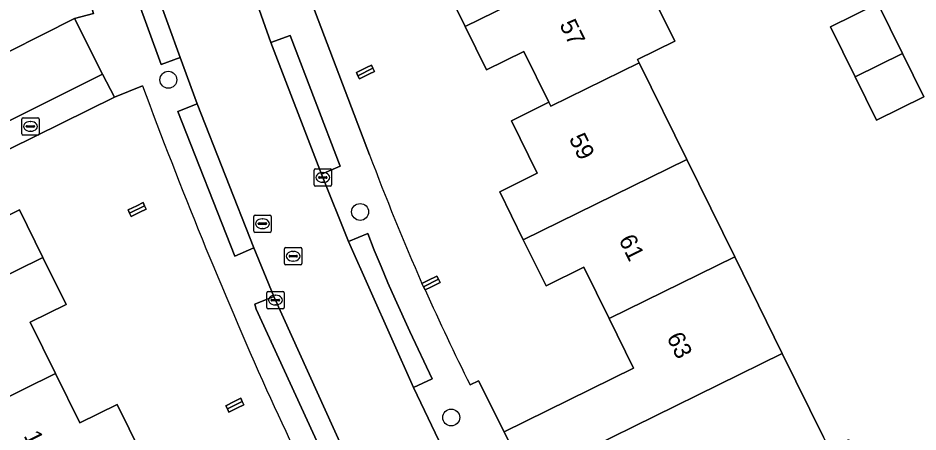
# Model space of a CAD drawing. Extents: x 157793 to 159380, y 380877 to 382313.
# Drawn here: x 158362 to 158414.2, y 381566.4 to 381590.4 of the extents above; entities that cross this region are included whole.
import ezdxf

# ---------------------------------------------------------------- set-up
doc = ezdxf.new("R2010")
doc.units = 0
for name, color, linetype in [('IMGEO_Boom', 7, 'Continuous'), ('IMGEO_Erf', 7, 'Continuous'), ('IMGEO_Kolk', 7, 'Continuous'), ('IMGEO_Pand', 7, 'Continuous'), ('IMGEO_Pand_nummerreeks', 7, 'Continuous'), ('IMGEO_Rijbaan_lokaal_open', 7, 'Continuous'), ('IMGEO_Rioolput', 7, 'Continuous'), ('IMGEO_Voetpad_open', 7, 'Continuous')]:
    doc.layers.add(name, color=color, linetype=linetype)

msp = doc.modelspace()

# ---------------------------------------------------------------- linework, layer by layer
at = {"layer": 'IMGEO_Boom'}
for centre in [(158370.732, 381586.792), (158381.84, 381579.129), (158387.121, 381567.211)]:
    msp.add_circle(centre, 0.489, dxfattribs=at)
at = {"layer": 'IMGEO_Erf'}
for points in [[(158356.876, 381585.543), (158358.253, 381582.801), (158361.236, 381584.267), (158359.62, 381587.484), (158365.3, 381590.338), (158366.389, 381590.642), (158363.671, 381599.661), (158359.523, 381613.428)], [(158388.212, 381569.097), (158388.702, 381569.336), (158390.187, 381566.383), (158397.688, 381570.074), (158396.271, 381572.954), (158394.809, 381575.924), (158392.612, 381574.843), (158391.296, 381577.517), (158389.927, 381580.297), (158392.107, 381581.37), (158390.606, 381584.418), (158392.777, 381585.486), (158391.328, 381588.431), (158389.17, 381587.369), (158387.933, 381589.882), (158386.449, 381592.897), (158388.607, 381593.959), (158387.233, 381596.753), (158380.16, 381593.447), (158378.526, 381592.633), (158382.383, 381582.444)], [(158397.374, 381594.525), (158400.079, 381589.03), (158397.912, 381587.964), (158398.004, 381587.778), (158400.762, 381582.173), (158403.54, 381576.529), (158406.301, 381570.918), (158408.691, 381566.062), (158408.949, 381565.538), (158409.028, 381565.378), (158410.156, 381565.932), (158413.001, 381560.152), (158415.756, 381561.507)], [(158414.496, 381585.807), (158411.752, 381584.456), (158410.515, 381586.97), (158409.093, 381589.86), (158411.837, 381591.211)], [(158369.236, 381586.441), (158367.61, 381585.777), (158358.447, 381581.259)], [(158359.962, 381578.192), (158362.103, 381579.249), (158363.465, 381576.49), (158364.809, 381573.766), (158362.727, 381572.738), (158364.193, 381569.769), (158365.607, 381566.904), (158367.759, 381567.966), (158369.156, 381565.135)], [(158385.424, 381574.982), (158385.755, 381575.145), (158386.292, 381575.41), (158386.381, 381575.228), (158386.475, 381575.038), (158385.938, 381574.773), (158385.607, 381574.61)]]:
    msp.add_lwpolyline(points, dxfattribs=at)
for points in [[(158382.387, 381587.133), (158381.808, 381586.847), (158381.718, 381587.029), (158381.625, 381587.219), (158382.204, 381587.505), (158382.493, 381587.647), (158382.581, 381587.467), (158382.676, 381587.275)], [(158368.396, 381579.242), (158368.897, 381579.489), (158369.264, 381579.67), (158369.355, 381579.485), (158369.447, 381579.298), (158369.081, 381579.117), (158368.579, 381578.87), (158368.489, 381579.053)], [(158374.24, 381567.523), (158374.149, 381567.708), (158374.057, 381567.895), (158374.546, 381568.136), (158374.925, 381568.323), (158375.017, 381568.135), (158375.108, 381567.951), (158374.729, 381567.764)]]:
    msp.add_lwpolyline(points, close=True, dxfattribs=at)
for centre, radius, start, end in [((158646.568, 381689.148), 295.739, 200.32153, 204.01013), ((158536.316, 381640.826), 164.633, 200.77015, 203.57474), ((158534.872, 381641.769), 163.678, 204.22437, 206.35893), ((158919.563, 381819.876), 598.364, 204.808304, 206.427269)]:
    msp.add_arc(centre, radius, start, end, dxfattribs=at)
at = {"layer": 'IMGEO_Kolk'}
for p, q in [((158362.242, 381583.661), (158362.242, 381584.513)), ((158362.317, 381584.587), (158363.169, 381584.587)), ((158363.243, 381584.513), (158363.243, 381583.661)), ((158362.501, 381584.081), (158362.501, 381584.093)), ((158362.939, 381584.044), (158362.541, 381584.044)), ((158362.544, 381584.13), (158362.942, 381584.13)), ((158362.73, 381584.367), (158362.755, 381584.367)), ((158362.985, 381584.093), (158362.985, 381584.081)), ((158363.169, 381583.587), (158362.317, 381583.587)), ((158362.753, 381583.807), (158362.728, 381583.807)), ((158379.18, 381580.701), (158379.18, 381581.553)), ((158379.255, 381581.627), (158380.107, 381581.627)), ((158379.668, 381581.407), (158379.693, 381581.407)), ((158380.181, 381581.553), (158380.181, 381580.701)), ((158379.439, 381581.121), (158379.439, 381581.133)), ((158379.877, 381581.084), (158379.479, 381581.084)), ((158379.482, 381581.17), (158379.88, 381581.17)), ((158379.691, 381580.847), (158379.666, 381580.847)), ((158379.923, 381581.133), (158379.923, 381581.121)), ((158380.107, 381580.627), (158379.255, 381580.627)), ((158376.509, 381574.518), (158377.361, 381574.518)), ((158376.434, 381573.592), (158376.434, 381574.444)), ((158376.693, 381574.012), (158376.693, 381574.024)), ((158376.736, 381574.061), (158377.134, 381574.061)), ((158376.922, 381574.298), (158376.947, 381574.298)), ((158377.177, 381574.024), (158377.177, 381574.012)), ((158377.435, 381574.444), (158377.435, 381573.592)), ((158377.361, 381573.518), (158376.509, 381573.518)), ((158377.131, 381573.975), (158376.733, 381573.975)), ((158376.945, 381573.738), (158376.92, 381573.738))]:
    msp.add_line(p, q, dxfattribs=at)
for points in [[(158362.242, 381583.661), (158362.242, 381584.513)], [(158362.317, 381584.587), (158363.169, 381584.587)], [(158363.243, 381584.513), (158363.243, 381583.661)], [(158363.169, 381583.587), (158362.317, 381583.587)], [(158379.18, 381580.701), (158379.18, 381581.553)], [(158379.255, 381581.627), (158380.107, 381581.627)], [(158380.181, 381581.553), (158380.181, 381580.701)], [(158380.107, 381580.627), (158379.255, 381580.627)], [(158376.509, 381574.518), (158377.361, 381574.518)], [(158376.434, 381573.592), (158376.434, 381574.444)], [(158377.435, 381574.444), (158377.435, 381573.592)], [(158377.361, 381573.518), (158376.509, 381573.518)]]:
    msp.add_lwpolyline(points, dxfattribs=at)
for centre, radius, start, end in [((158362.319, 381584.511), 0.0765, 91.552, 178.448), ((158362.319, 381584.511), 0.0765, 91.552, 178.448), ((158363.167, 381584.511), 0.0765, 1.552, 88.448), ((158363.167, 381584.511), 0.0765, 1.552, 88.448), ((158362.541, 381584.09), 0.0403, 85.8775, 175.7526), ((158362.538, 381584.08), 0.0366, 178.938, 274.7102), ((158362.942, 381584.087), 0.043, 264.8664, 352.4533), ((158362.946, 381584.092), 0.0386, 1.7309, 96.639), ((158362.319, 381583.663), 0.0765, 181.552, 268.448), ((158362.319, 381583.663), 0.0765, 181.552, 268.448), ((158363.167, 381583.663), 0.0765, 271.552, 358.448), ((158363.167, 381583.663), 0.0765, 271.552, 358.448), ((158379.257, 381581.551), 0.0765, 91.552, 178.448), ((158379.257, 381581.551), 0.0765, 91.552, 178.448), ((158380.105, 381581.551), 0.0765, 1.552, 88.448), ((158380.105, 381581.551), 0.0765, 1.552, 88.448), ((158379.479, 381581.13), 0.0403, 85.8775, 175.7526), ((158379.476, 381581.12), 0.0366, 178.938, 274.7102), ((158379.88, 381581.127), 0.043, 264.8664, 352.4533), ((158379.884, 381581.132), 0.0386, 1.7309, 96.639), ((158379.257, 381580.703), 0.0765, 181.552, 268.448), ((158379.257, 381580.703), 0.0765, 181.552, 268.448), ((158380.105, 381580.703), 0.0765, 271.552, 358.448), ((158380.105, 381580.703), 0.0765, 271.552, 358.448), ((158376.511, 381574.442), 0.0765, 91.552, 178.448), ((158376.511, 381574.442), 0.0765, 91.552, 178.448), ((158377.359, 381574.442), 0.0765, 1.552, 88.448), ((158377.359, 381574.442), 0.0765, 1.552, 88.448), ((158376.733, 381574.021), 0.0403, 85.8775, 175.7526), ((158376.73, 381574.011), 0.0366, 178.938, 274.7102), ((158377.134, 381574.018), 0.043, 264.8664, 352.4533), ((158377.138, 381574.023), 0.0386, 1.7309, 96.639), ((158376.511, 381573.594), 0.0765, 181.552, 268.448), ((158376.511, 381573.594), 0.0765, 181.552, 268.448), ((158377.359, 381573.594), 0.0765, 271.552, 358.448), ((158377.359, 381573.594), 0.0765, 271.552, 358.448)]:
    msp.add_arc(centre, radius, start, end, dxfattribs=at)
for centre, major_axis, ratio, start_param, end_param in [((158362.729, 381584.087), (-0.387, 0.002), 0.722429, 4.712389, 7.853982), ((158362.754, 381584.087), (-0.39, 0.002), 0.717154, 1.570796, 4.712389), ((158379.667, 381581.127), (-0.387, 0.002), 0.722429, 4.712389, 7.853982), ((158379.692, 381581.127), (-0.39, 0.002), 0.717154, 1.570796, 4.712389), ((158376.921, 381574.018), (-0.387, 0.002), 0.722429, 4.712389, 7.853982), ((158376.946, 381574.018), (-0.39, 0.002), 0.717154, 1.570796, 4.712389)]:
    msp.add_ellipse(centre, major_axis=major_axis, ratio=ratio, start_param=start_param, end_param=end_param, dxfattribs=at)
at = {"layer": 'IMGEO_Pand'}
for points in [[(158387.933, 381589.882), (158397.374, 381594.525), (158396.722, 381595.85), (158394.514, 381600.336), (158387.233, 381596.753), (158388.607, 381593.959), (158386.449, 381592.897)], [(158387.933, 381589.882), (158389.17, 381587.369), (158391.328, 381588.431), (158392.777, 381585.486), (158392.885, 381585.266), (158398.004, 381587.778), (158397.912, 381587.964), (158400.079, 381589.03), (158397.374, 381594.525)], [(158410.515, 381586.97), (158413.259, 381588.32), (158411.837, 381591.211), (158409.093, 381589.86)], [(158366.916, 381587.12), (158365.3, 381590.338), (158359.62, 381587.484), (158361.236, 381584.267)], [(158410.515, 381586.97), (158411.752, 381584.456), (158414.496, 381585.807), (158413.259, 381588.32)], [(158381.718, 381587.029), (158382.581, 381587.467), (158382.493, 381587.647), (158382.204, 381587.505), (158381.625, 381587.219)], [(158400.762, 381582.173), (158398.004, 381587.778), (158392.885, 381585.266), (158392.777, 381585.486), (158390.606, 381584.418), (158392.107, 381581.37), (158389.927, 381580.297), (158391.296, 381577.517)], [(158382.581, 381587.467), (158381.718, 381587.029), (158381.808, 381586.847), (158382.387, 381587.133), (158382.676, 381587.275)], [(158400.762, 381582.173), (158391.296, 381577.517), (158392.612, 381574.843), (158394.809, 381575.924), (158396.271, 381572.954), (158403.54, 381576.529)], [(158354.103, 381571.867), (158363.465, 381576.49), (158362.103, 381579.249), (158359.962, 381578.192), (158358.447, 381581.259), (158351.226, 381577.694)], [(158368.489, 381579.053), (158369.355, 381579.485), (158369.264, 381579.67), (158368.897, 381579.489), (158368.396, 381579.242)], [(158369.355, 381579.485), (158368.489, 381579.053), (158368.579, 381578.87), (158369.081, 381579.117), (158369.447, 381579.298)], [(158356.912, 381566.175), (158364.193, 381569.769), (158362.727, 381572.738), (158364.809, 381573.766), (158363.465, 381576.49), (158354.103, 381571.867)], [(158391.533, 381563.648), (158406.301, 381570.918), (158403.54, 381576.529), (158396.271, 381572.954), (158397.688, 381570.074), (158390.187, 381566.383)], [(158385.517, 381574.792), (158386.381, 381575.228), (158386.292, 381575.41), (158385.755, 381575.145), (158385.424, 381574.982)], [(158386.381, 381575.228), (158385.517, 381574.792), (158385.607, 381574.61), (158385.938, 381574.773), (158386.475, 381575.038)], [(158409.028, 381565.378), (158408.949, 381565.538), (158408.691, 381566.062), (158406.301, 381570.918), (158391.533, 381563.648), (158392.879, 381560.912), (158400.34, 381564.584), (158401.927, 381561.36), (158403.032, 381561.904), (158402.93, 381562.112), (158409.036, 381565.124), (158408.935, 381565.332)], [(158364.193, 381569.769), (158356.912, 381566.175), (158354.295, 381564.883), (158355.562, 381562.319), (158358.171, 381563.626), (158359.724, 381560.479), (158369.156, 381565.135), (158367.759, 381567.966), (158365.607, 381566.904)], [(158375.017, 381568.135), (158374.925, 381568.323), (158374.546, 381568.136), (158374.057, 381567.895), (158374.149, 381567.708)], [(158375.017, 381568.135), (158374.149, 381567.708), (158374.24, 381567.523), (158374.729, 381567.764), (158375.108, 381567.951)]]:
    msp.add_lwpolyline(points, close=True, dxfattribs=at)
at = {"layer": 'IMGEO_Rijbaan_lokaal_open'}
msp.add_lwpolyline([(158386.819, 381564.982), (158384.933, 381568.948), (158381.167, 381577.418), (158379.602, 381581.325), (158376.667, 381588.951), (158374.56, 381594.93), (158371.964, 381603.521), (158369.282, 381612.393), (158368.776, 381614.35), (158363.671, 381612.88), (158364.288, 381610.829), (158368.864, 381595.592), (158369.995, 381592.049), (158371.408, 381588.08), (158372.398, 381585.387), (158375.686, 381577.039), (158376.843, 381574.222), (158380.835, 381565.391), (158382.561, 381561.814), (158386.047, 381554.706), (158388.014, 381550.791), (158391.624, 381543.519), (158392.052, 381542.802), (158392.965, 381540.911)], dxfattribs=at)
at = {"layer": 'IMGEO_Rioolput'}
for p, q in [((158375.681, 381578.02), (158375.681, 381578.872)), ((158375.756, 381578.946), (158376.608, 381578.946)), ((158376.169, 381578.726), (158376.194, 381578.726)), ((158376.682, 381578.872), (158376.682, 381578.02)), ((158375.94, 381578.44), (158375.94, 381578.452)), ((158376.378, 381578.403), (158375.98, 381578.403)), ((158375.983, 381578.489), (158376.381, 381578.489)), ((158376.192, 381578.166), (158376.167, 381578.166)), ((158376.424, 381578.452), (158376.424, 381578.44)), ((158376.608, 381577.946), (158375.756, 381577.946)), ((158377.464, 381576.136), (158377.464, 381576.988)), ((158377.539, 381577.062), (158378.391, 381577.062)), ((158377.766, 381576.605), (158378.164, 381576.605)), ((158377.952, 381576.842), (158377.977, 381576.842)), ((158378.465, 381576.988), (158378.465, 381576.136)), ((158377.723, 381576.556), (158377.723, 381576.568)), ((158378.161, 381576.519), (158377.763, 381576.519)), ((158377.975, 381576.282), (158377.95, 381576.282)), ((158378.207, 381576.568), (158378.207, 381576.556)), ((158378.391, 381576.062), (158377.539, 381576.062))]:
    msp.add_line(p, q, dxfattribs=at)
for points in [[(158375.681, 381578.02), (158375.681, 381578.872)], [(158375.756, 381578.946), (158376.608, 381578.946)], [(158376.682, 381578.872), (158376.682, 381578.02)], [(158376.608, 381577.946), (158375.756, 381577.946)], [(158377.464, 381576.136), (158377.464, 381576.988)], [(158377.539, 381577.062), (158378.391, 381577.062)], [(158378.465, 381576.988), (158378.465, 381576.136)], [(158378.391, 381576.062), (158377.539, 381576.062)]]:
    msp.add_lwpolyline(points, dxfattribs=at)
for centre, radius, start, end in [((158375.758, 381578.87), 0.0765, 91.552, 178.448), ((158375.758, 381578.87), 0.0765, 91.552, 178.448), ((158376.606, 381578.87), 0.0765, 1.552, 88.448), ((158376.606, 381578.87), 0.0765, 1.552, 88.448), ((158375.98, 381578.449), 0.0403, 85.8775, 175.7526), ((158375.977, 381578.439), 0.0366, 178.938, 274.7102), ((158376.381, 381578.446), 0.043, 264.8664, 352.4533), ((158376.385, 381578.451), 0.0386, 1.7309, 96.639), ((158375.758, 381578.022), 0.0765, 181.552, 268.448), ((158375.758, 381578.022), 0.0765, 181.552, 268.448), ((158376.606, 381578.022), 0.0765, 271.552, 358.448), ((158376.606, 381578.022), 0.0765, 271.552, 358.448), ((158377.541, 381576.986), 0.0765, 91.552, 178.448), ((158377.541, 381576.986), 0.0765, 91.552, 178.448), ((158377.763, 381576.565), 0.0403, 85.8775, 175.7526), ((158378.168, 381576.567), 0.0386, 1.7309, 96.639), ((158378.389, 381576.986), 0.0765, 1.552, 88.448), ((158378.389, 381576.986), 0.0765, 1.552, 88.448), ((158377.541, 381576.138), 0.0765, 181.552, 268.448), ((158377.541, 381576.138), 0.0765, 181.552, 268.448), ((158377.76, 381576.555), 0.0366, 178.938, 274.7102), ((158378.164, 381576.562), 0.043, 264.8664, 352.4533), ((158378.389, 381576.138), 0.0765, 271.552, 358.448), ((158378.389, 381576.138), 0.0765, 271.552, 358.448)]:
    msp.add_arc(centre, radius, start, end, dxfattribs=at)
for centre, major_axis, ratio, start_param, end_param in [((158376.168, 381578.446), (-0.387, 0.002), 0.722429, 4.712389, 7.853982), ((158376.193, 381578.446), (-0.39, 0.002), 0.717154, 1.570796, 4.712389), ((158377.951, 381576.562), (-0.387, 0.002), 0.722429, 4.712389, 7.853982), ((158377.976, 381576.562), (-0.39, 0.002), 0.717154, 1.570796, 4.712389)]:
    msp.add_ellipse(centre, major_axis=major_axis, ratio=ratio, start_param=start_param, end_param=end_param, dxfattribs=at)
at = {"layer": 'IMGEO_Voetpad_open'}
for points in [[(158359.523, 381613.428), (158363.671, 381599.661), (158366.389, 381590.642), (158365.3, 381590.338), (158366.916, 381587.12), (158367.61, 381585.777), (158369.236, 381586.441)], [(158374.56, 381594.93), (158376.667, 381588.951), (158377.786, 381589.363), (158380.682, 381581.779), (158379.602, 381581.325), (158381.167, 381577.418), (158382.279, 381577.87), (158382.66, 381576.914), (158383.053, 381575.963), (158383.455, 381575.016), (158383.868, 381574.073), (158384.725, 381572.202), (158386.008, 381569.445), (158384.933, 381568.948), (158386.819, 381564.982), (158387.899, 381565.529), (158391.435, 381558.264), (158390.388, 381557.763), (158392.105, 381554.248), (158393.177, 381554.8), (158396.917, 381547.243), (158395.863, 381546.7), (158397.356, 381543.737), (158402.431, 381546.2)], [(158382.383, 381582.444), (158378.526, 381592.633), (158380.16, 381593.447), (158379.644, 381594.891)], [(158392.965, 381540.911), (158392.052, 381542.802), (158391.624, 381543.519), (158390.547, 381543.006), (158386.953, 381550.259), (158388.014, 381550.791), (158386.047, 381554.706), (158384.979, 381554.194), (158381.459, 381561.337), (158382.561, 381561.814), (158380.835, 381565.391), (158379.757, 381564.906), (158375.828, 381573.501), (158375.741, 381573.782), (158376.843, 381574.222), (158375.686, 381577.039), (158374.58, 381576.567), (158371.288, 381584.953), (158372.398, 381585.387), (158371.408, 381588.08), (158370.307, 381587.67), (158368.88, 381591.616), (158369.995, 381592.049)], [(158411.837, 381591.211), (158413.259, 381588.32), (158414.496, 381585.807)], [(158385.607, 381574.61), (158385.517, 381574.792), (158385.424, 381574.982)], [(158398.533, 381548.059), (158392.958, 381559.198), (158392.218, 381560.663), (158392.879, 381560.912), (158391.533, 381563.648), (158390.187, 381566.383), (158388.702, 381569.336), (158388.212, 381569.097)]]:
    msp.add_lwpolyline(points, dxfattribs=at)
for points in [[(158369.995, 381592.049), (158368.88, 381591.616), (158370.307, 381587.67), (158371.408, 381588.08)], [(158376.667, 381588.951), (158379.602, 381581.325), (158380.682, 381581.779), (158377.786, 381589.363)], [(158367.61, 381585.777), (158366.916, 381587.12), (158361.236, 381584.267), (158358.253, 381582.801), (158355.555, 381581.446), (158352.725, 381580.024), (158346.976, 381577.187), (158344.273, 381575.83), (158341.498, 381574.436), (158340.289, 381573.852), (158340.953, 381572.506), (158343.745, 381573.884), (158351.226, 381577.694), (158358.447, 381581.259)], [(158372.398, 381585.387), (158371.288, 381584.953), (158374.58, 381576.567), (158375.686, 381577.039)], [(158383.868, 381574.073), (158383.455, 381575.016), (158383.053, 381575.963), (158382.66, 381576.914), (158382.279, 381577.87), (158381.167, 381577.418), (158384.933, 381568.948), (158386.008, 381569.445), (158384.725, 381572.202)], [(158376.843, 381574.222), (158375.741, 381573.782), (158375.828, 381573.501), (158379.757, 381564.906), (158380.835, 381565.391)]]:
    msp.add_lwpolyline(points, close=True, dxfattribs=at)
for centre, radius, start, end in [((158646.568, 381689.148), 295.739, 200.32153, 204.01013), ((158536.316, 381640.826), 164.633, 200.77015, 203.57474), ((158534.872, 381641.769), 163.678, 204.22437, 206.35893), ((158919.563, 381819.876), 598.364, 204.808304, 206.427269)]:
    msp.add_arc(centre, radius, start, end, dxfattribs=at)

# ---------------------------------------------------------------- texts
at = {"layer": 'IMGEO_Pand_nummerreeks'}
for s, rotation, p in [('57', 296.1998, (158393.369, 381589.992)), ('59', 296.1501, (158393.919, 381583.388)), ('61', 296.1501, (158396.8, 381577.522)), ('63', 296.1501, (158399.58, 381571.859)), ('16', 296.5621, (158362.331, 381566.156))]:
    msp.add_text(s, height=1, rotation=rotation, dxfattribs=at).set_placement(p)

doc.saveas('drawing.dxf')
